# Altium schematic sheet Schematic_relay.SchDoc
size A; SheetNumber: 1; SheetTotal: 1
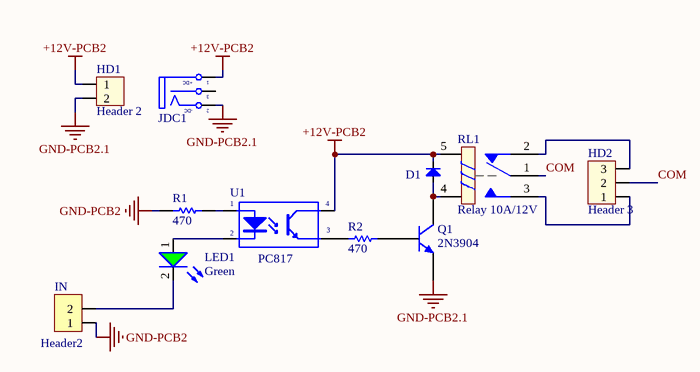
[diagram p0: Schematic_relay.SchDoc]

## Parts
D1  Diode  [DIO-1A-SMALL]  (value not drawn)
HD1  Header 2  [HED2]
HD2  Header 3  [HED3B]
IN  Header2  [HDR2]
JDC1  Jack DC  [DC-IN]  (value not drawn)
LED1  value Green  [LED3G]  (hidden comment: LED_G_3)
Q1  2N3904  [TO-92A]
R1  value 470  [RES 1/2W]  (hidden comment: RESISTOR)
R2  value 470  [RES 1/2W]  (hidden comment: RESISTOR)
RL1  Relay 10A/12V  [RELAY 5]
U1  PC817  [DIP4]

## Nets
+12V-PCB2: D1.2(K) HD1.1 JDC1.1(T) RL1.5 U1.4(C)
GND-PCB2: IN.1 R1.1
GND-PCB2.1: HD1.2 JDC1.2(TN) Q1.1(E)
COM: HD2.2 RL1.1
NetD1_1: D1.1(A) Q1.3(C) RL1.4
NetHD2_1: HD2.1 RL1.3
NetHD2_3: HD2.3 RL1.2
NetIN_2: IN.2 LED1.2(K)
NetLED1_1: LED1.1(A) U1.2(K)
NetQ1_2: Q1.2(B) R2.2
NetR1_2: R1.2 U1.1(A)
NetR2_1: R2.1 U1.3(E)

Not connected (* = marked no-connect by the designer): JDC1 3(S)

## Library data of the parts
D1 = Diode: Default Diode; Code - JEDEC: DO-214-AB; Value: 1N5007
HD1 = Hed2: Header 2 (Green)
HD2 = Hed3: Header 3 (Green)
IN = Header2: Header IDC, 2 x 1 Pin Vertical 2.54mm Pitch (Non-Boxed, Male); Manufacturer: W¨¹rth Elektronik eiSos GmbH; partNo: 613002143121; ComponentLink1 Description: Manufacturer; ComponentLink2 Description: Datasheet; NoPins: 02
JDC1 = Jack DC: Jack DC input; Value: Jac DC
LED1 = LED_GREEN_3MM: LED Green 3mm
Q1 = 2N3904: NPN General Purpose Amplifier
RL1 = Relay 5: Relay SPDT,10A - 12VDC 5 Pin; Value: Relay SPDT, 10A, 12V
U1 = PC817: Single Opto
